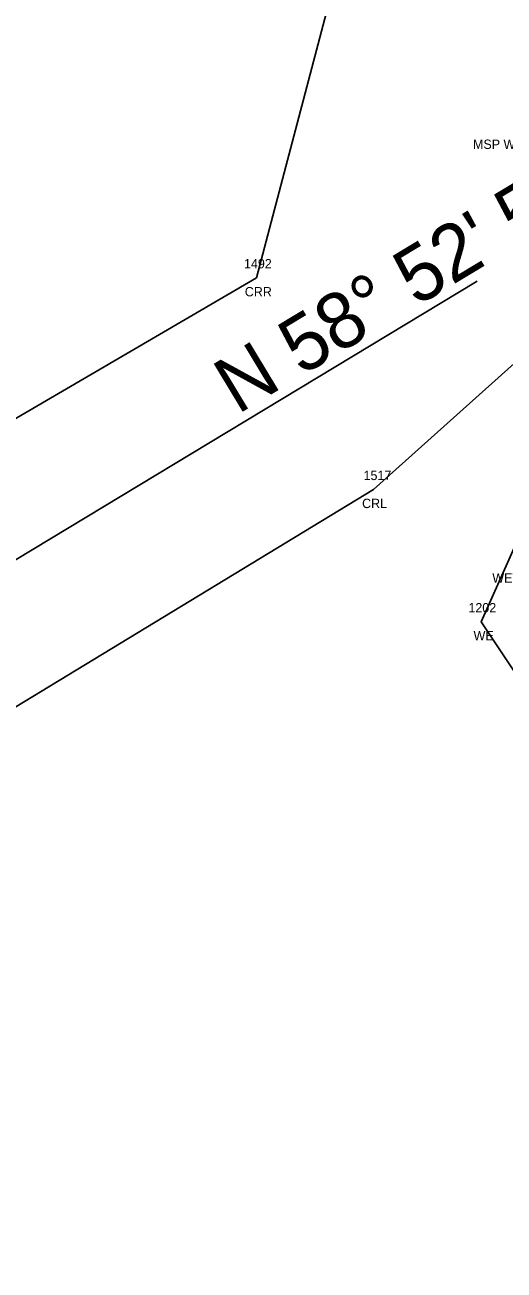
# Model space of a CAD drawing. Extents: x 2521558 to 2524785, y 882711 to 887632.
# Drawn here: x 2523707.4 to 2523758.7, y 884993.3 to 885126.7 of the extents above; entities that cross this region are included whole.
import ezdxf

# ---------------------------------------------------------------- set-up
doc = ezdxf.new("R2010")
doc.units = 0
for name, color, linetype in [('RD_EX_H2O', 7, 'Continuous'), ('RD_EX_H2O_txCode', 7, 'Continuous'), ('RD_EX_H2O_WetLd_txCode', 7, 'Continuous'), ('RD_EX_Misc_txCode', 7, 'Continuous'), ('RD_HC_Cl', 7, 'Continuous'), ('RD_HC_Data', 7, 'Continuous'), ('RD_SMD_Locator', 7, 'Continuous')]:
    doc.layers.add(name, color=color, linetype=linetype)

msp = doc.modelspace()

# ---------------------------------------------------------------- linework, layer by layer
at = {"layer": 'RD_EX_H2O'}
for points in [[(2523582.82, 884766.34), (2523598.11, 884856.98), (2523627.59, 884901.75), (2523623.76, 884928.28), (2523586.58, 884955.43), (2523600.94, 884974.12), (2523633.05, 884997.68), (2523679.17, 885037.05), (2523744.72, 885076.89), (2523769.38, 885099), (2523825.47, 885108.66), (2523825.47, 885108.66), (2523845.24, 885110.83), (2523890.25, 885154.93)], [(2523741.75, 885135.92), (2523732.18, 885099.57), (2523664.9, 885060.26), (2523614.86, 885022.02), (2523558.95, 884972.63), (2523560.62, 884942.42), (2523490.01, 884911.76)], [(2523792.73, 884941.12), (2523763.67, 885051.56), (2523756.26, 885062.72), (2523770.47, 885094.55), (2523817.57, 885105.71), (2523827.83, 885106)]]:
    msp.add_lwpolyline(points, dxfattribs=at)
at = {"layer": 'RD_HC_Cl'}
msp.add_line((2523672.04, 885048.63), (2523755.81, 885099.2), dxfattribs=at)
at = {"layer": 'RD_SMD_Locator'}
for centre in [(2523732.18, 885099.57), (2523744.72, 885076.89), (2523756.26, 885062.72)]:
    msp.add_circle(centre, 0.001, dxfattribs=at)

# ---------------------------------------------------------------- texts
at = {"layer": 'RD_EX_H2O_txCode'}
for s, p in [('1492', (2523730.84, 885100.57)), ('CRR', (2523730.93, 885097.57)), ('1517', (2523743.65, 885077.89)), ('CRL', (2523743.49, 885074.89)), ('1202', (2523754.88, 885063.72)), ('WE', (2523755.43, 885060.72))]:
    msp.add_text(s, height=1, dxfattribs=at).set_placement(p)
at = {"layer": 'RD_EX_H2O_WetLd_txCode'}
msp.add_text('WETB B11', height=1, dxfattribs=at).set_placement((2523757.44, 885066.9))
at = {"layer": 'RD_EX_Misc_txCode'}
msp.add_text('MSP WATER ELEV 3-26-2014', height=1, dxfattribs=at).set_placement((2523755.37, 885113.37))
at = {"layer": 'RD_HC_Data'}
msp.add_text('N 58%%d 52\' 54" E', height=6, rotation=31.1184, dxfattribs=at).set_placement((2523730.14, 885084.87))

doc.saveas('drawing.dxf')
